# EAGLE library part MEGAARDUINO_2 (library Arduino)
The Arduino Mega is a microcontroller board based on the ATmega1280. - 54 digital input/output pins (of which 14 can be used as PWM outputs) - 16 analog inputs - 4 UARTs (hardware serial ports) - 16 MHz crystal oscillator - USB connection - power jack - ICSP header - reset button It contains everything needed to support the microcontroller; simply connect it to a computer with a USB cable or power it with a AC-to-DC adapter or battery to get started. The Mega is compatible with most shields designed for the Arduino Duemilanove or Diecimila. http://arduino.cc/en/Main/ArduinoBoardMega
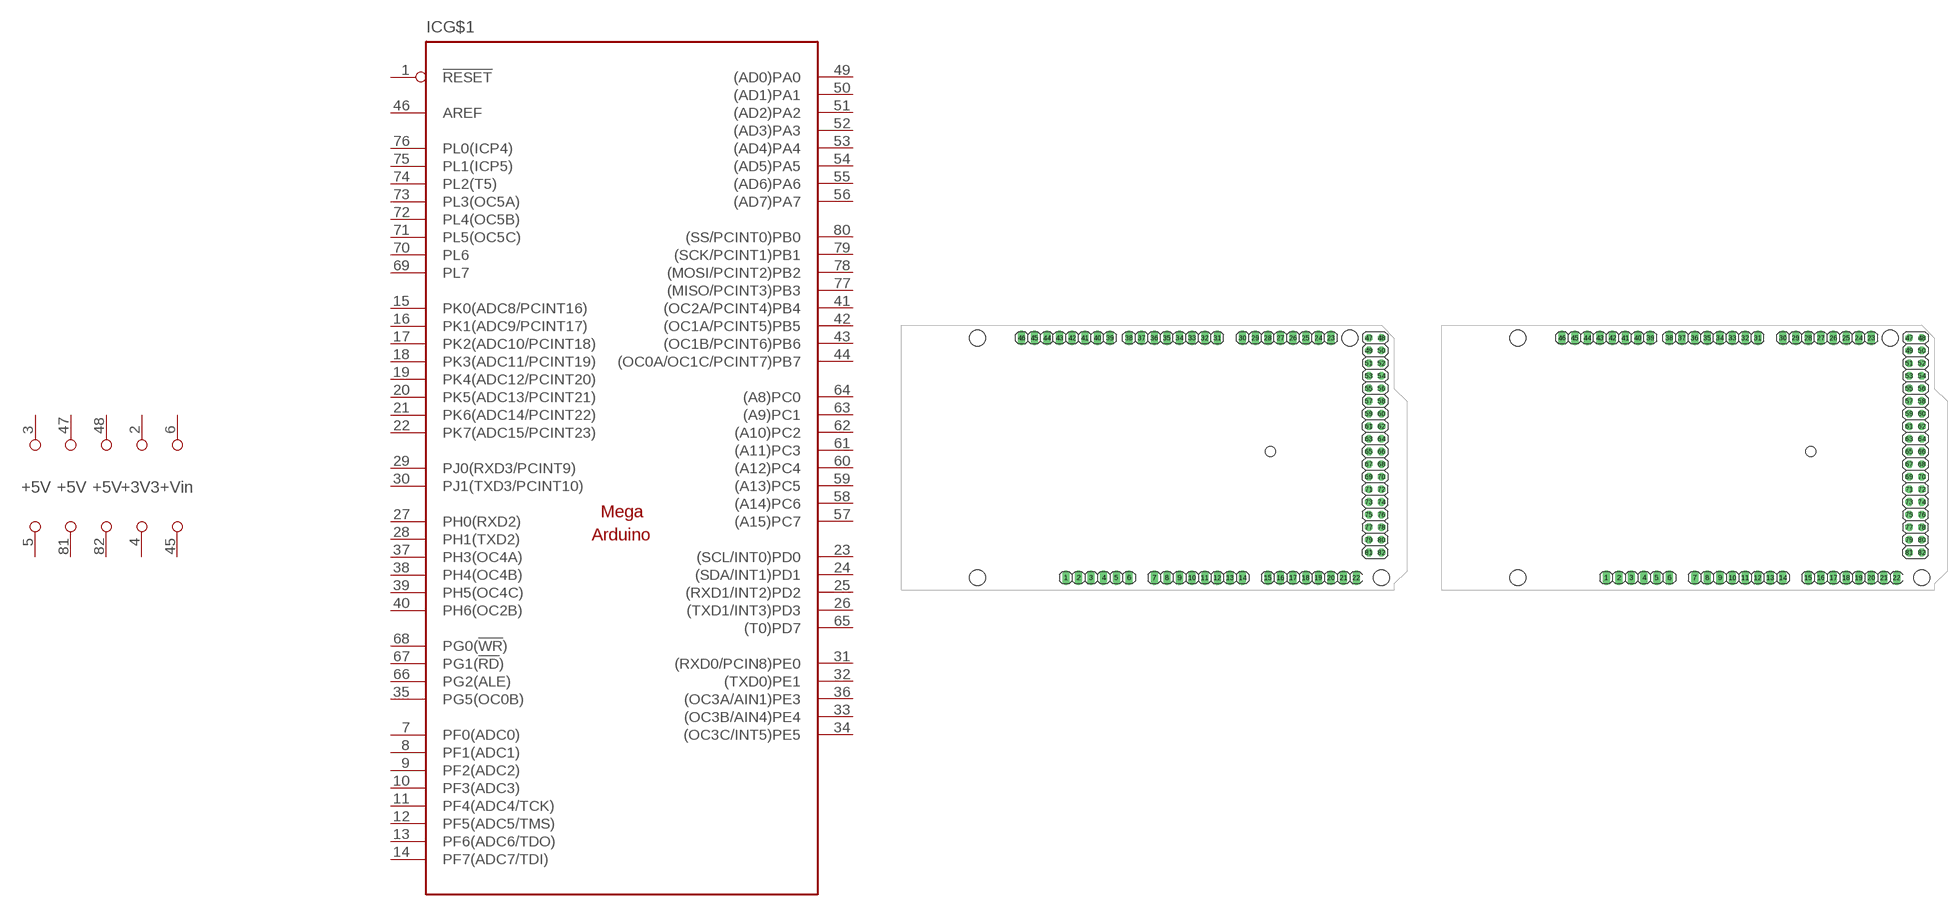
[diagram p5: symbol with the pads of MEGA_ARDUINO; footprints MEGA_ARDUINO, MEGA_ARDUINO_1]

Designator prefix IC; gates G$1=MEGAARDUINO_2 G$2=PWR5V G$3=PWR5V G$4=PWR5V G$5=PWR3V3 G$6=PWRVIN

## MEGAARDUINO_20  [MEGA_ARDUINO]
1  G$1:!RESET
2  G$5:+3V3  pwr
3  G$2:+5V  pwr
4  G$5:GND  pwr
5  G$2:GND  pwr
6  G$6:+VIN  pwr
7  G$1:PF0(ADC0)
8  G$1:PF1(ADC1)
9  G$1:PF2(ADC2)
10  G$1:PF3(ADC3)
11  G$1:PF4(ADC4/TCK)
12  G$1:PF5(ADC5/TMS)
13  G$1:PF6(ADC6/TDO)
14  G$1:PF7(ADC7/TDI)
15  G$1:PK0(ADC8/PCINT16)
16  G$1:PK1(ADC9/PCINT17)
17  G$1:PK2(ADC10/PCINT18)
18  G$1:PK3(ADC11/PCINT19)
19  G$1:PK4(ADC12/PCINT20)
20  G$1:PK5(ADC13/PCINT21)
21  G$1:PK6(ADC14/PCINT22)
22  G$1:PK7(ADC15/PCINT23)
23  G$1:(SCL/INT0)PD0
24  G$1:(SDA/INT1)PD1
25  G$1:(RXD1/INT2)PD2
26  G$1:(TXD1/INT3)PD3
27  G$1:PH0(RXD2)
28  G$1:PH1(TXD2)
29  G$1:PJ0(RXD3/PCINT9)
30  G$1:PJ1(TXD3/PCINT10)
31  G$1:(RXD0/PCIN8)PE0
32  G$1:(TXD0)PE1
33  G$1:(OC3B/AIN4)PE4
34  G$1:(OC3C/INT5)PE5
35  G$1:PG5(OC0B)
36  G$1:(OC3A/AIN1)PE3
37  G$1:PH3(OC4A)
38  G$1:PH4(OC4B)
39  G$1:PH5(OC4C)
40  G$1:PH6(OC2B)
41  G$1:(OC2A/PCINT4)PB4
42  G$1:(OC1A/PCINT5)PB5
43  G$1:(OC1B/PCINT6)PB6
44  G$1:(OC0A/OC1C/PCINT7)PB7
45  G$6:GND  pwr
46  G$1:AREF
47  G$3:+5V  pwr
48  G$4:+5V  pwr
49  G$1:(AD0)PA0
50  G$1:(AD1)PA1
51  G$1:(AD2)PA2
52  G$1:(AD3)PA3
53  G$1:(AD4)PA4
54  G$1:(AD5)PA5
55  G$1:(AD6)PA6
56  G$1:(AD7)PA7
57  G$1:(A15)PC7
58  G$1:(A14)PC6
59  G$1:(A13)PC5
60  G$1:(A12)PC4
61  G$1:(A11)PC3
62  G$1:(A10)PC2
63  G$1:(A9)PC1
64  G$1:(A8)PC0
65  G$1:(T0)PD7
66  G$1:PG2(ALE)
67  G$1:PG1(!RD!)
68  G$1:PG0(!WR!)
69  G$1:PL7
70  G$1:PL6
71  G$1:PL5(OC5C)
72  G$1:PL4(OC5B)
73  G$1:PL3(OC5A)
74  G$1:PL2(T5)
75  G$1:PL1(ICP5)
76  G$1:PL0(ICP4)
77  G$1:(MISO/PCINT3)PB3
78  G$1:(MOSI/PCINT2)PB2
79  G$1:(SCK/PCINT1)PB1
80  G$1:(SS/PCINT0)PB0
81  G$3:GND  pwr
82  G$4:GND  pwr

## MEGAARDUINO_21  [MEGA_ARDUINO_1]
Pads as for MEGA_ARDUINO

## MEGAARDUINO_22  [MEGA_ARDUINO_2]
Pads as for MEGA_ARDUINO

## Footprint MEGA_ARDUINO (pad centres in mm)
drill 1.016 long: 1 33.02,2.54; 2 35.56,2.54; 3 38.1,2.54; 4 40.64,2.54; 5 43.18,2.54; 6 45.72,2.54; 7 50.8,2.54; 8 53.34,2.54; 9 55.88,2.54; 10 58.42,2.54; 11 60.96,2.54; 12 63.5,2.54; 13 66.04,2.54; 14 68.58,2.54; 15 73.66,2.54; 16 76.2,2.54; 17 78.74,2.54; 18 81.28,2.54; 19 83.82,2.54; 20 86.36,2.54; 21 88.9,2.54; 22 91.44,2.54; 23 86.36,50.8; 24 83.82,50.8; 25 81.28,50.8; 26 78.74,50.8; 27 76.2,50.8; 28 73.66,50.8; 29 71.12,50.8; 30 68.58,50.8; 31 63.5,50.8; 32 60.96,50.8; 33 58.42,50.8; 34 55.88,50.8; 35 53.34,50.8; 36 50.8,50.8; 37 48.26,50.8; 38 45.72,50.8; 39 41.91,50.8; 40 39.37,50.8; 41 36.83,50.8; 42 34.29,50.8; 43 31.75,50.8; 44 29.21,50.8; 45 26.67,50.8; 46 24.13,50.8
drill 1.016 octagon: 47 93.98,50.8; 48 96.52,50.8; 49 93.98,48.26; 50 96.52,48.26; 51 93.98,45.72; 52 96.52,45.72; 53 93.98,43.18; 54 96.52,43.18; 55 93.98,40.64; 56 96.52,40.64; 57 93.98,38.1; 58 96.52,38.1; 59 93.98,35.56; 60 96.52,35.56; 61 93.98,33.02; 62 96.52,33.02; 63 93.98,30.48; 64 96.52,30.48; 65 93.98,27.94; 66 96.52,27.94; 67 93.98,25.4; 68 96.52,25.4; 69 93.98,22.86; 70 96.52,22.86; 71 93.98,20.32; 72 96.52,20.32; 73 93.98,17.78; 74 96.52,17.78; 75 93.98,15.24; 76 96.52,15.24; 77 93.98,12.7; 78 96.52,12.7; 79 93.98,10.16; 80 96.52,10.16; 81 93.98,7.62; 82 96.52,7.62
hole 3.2 at 15.24,50.8
hole 3.2 at 15.24,2.54
hole 3.2 at 90.17,50.8
hole 3.2 at 96.52,2.54
hole 2 at 74.168,27.94

## Footprint MEGA_ARDUINO_1 (pad centres in mm)
drill 1.016 long: 1 33.02,2.54; 2 35.56,2.54; 3 38.1,2.54; 4 40.64,2.54; 5 43.18,2.54; 6 45.72,2.54; 7 50.8,2.54; 8 53.34,2.54; 9 55.88,2.54; 10 58.42,2.54; 11 60.96,2.54; 12 63.5,2.54; 13 66.04,2.54; 14 68.58,2.54; 15 73.66,2.54; 16 76.2,2.54; 17 78.74,2.54; 18 81.28,2.54; 19 83.82,2.54; 20 86.36,2.54; 21 88.9,2.54; 22 91.44,2.54; 23 86.36,50.8; 24 83.82,50.8; 25 81.28,50.8; 26 78.74,50.8; 27 76.2,50.8; 28 73.66,50.8; 29 71.12,50.8; 30 68.58,50.8; 31 63.5,50.8; 32 60.96,50.8; 33 58.42,50.8; 34 55.88,50.8; 35 53.34,50.8; 36 50.8,50.8; 37 48.26,50.8; 38 45.72,50.8; 39 41.91,50.8; 40 39.37,50.8; 41 36.83,50.8; 42 34.29,50.8; 43 31.75,50.8; 44 29.21,50.8; 45 26.67,50.8; 46 24.13,50.8
drill 1.016 octagon: 47 93.98,50.8; 48 96.52,50.8; 49 93.98,48.26; 50 96.52,48.26; 51 93.98,45.72; 52 96.52,45.72; 53 93.98,43.18; 54 96.52,43.18; 55 93.98,40.64; 56 96.52,40.64; 57 93.98,38.1; 58 96.52,38.1; 59 93.98,35.56; 60 96.52,35.56; 61 93.98,33.02; 62 96.52,33.02; 63 93.98,30.48; 64 96.52,30.48; 65 93.98,27.94; 66 96.52,27.94; 67 93.98,25.4; 68 96.52,25.4; 69 93.98,22.86; 70 96.52,22.86; 71 93.98,20.32; 72 96.52,20.32; 73 93.98,17.78; 74 96.52,17.78; 75 93.98,15.24; 76 96.52,15.24; 77 93.98,12.7; 78 96.52,12.7; 79 93.98,10.16; 80 96.52,10.16; 81 93.98,7.62; 82 96.52,7.62
hole 3.2 at 15.24,50.8
hole 3.2 at 15.24,2.54
hole 3.2 at 90.17,50.8
hole 3.2 at 96.52,2.54
hole 2 at 74.168,27.94

## Footprint MEGA_ARDUINO_2 (pad centres in mm)
drill 1.016 long: 1 33.02,2.54; 2 35.56,2.54; 3 38.1,2.54; 4 40.64,2.54; 5 43.18,2.54; 6 45.72,2.54; 7 50.8,2.54; 8 53.34,2.54; 9 55.88,2.54; 10 58.42,2.54; 11 60.96,2.54; 12 63.5,2.54; 13 66.04,2.54; 14 68.58,2.54; 15 73.66,2.54; 16 76.2,2.54; 17 78.74,2.54; 18 81.28,2.54; 19 83.82,2.54; 20 86.36,2.54; 21 88.9,2.54; 22 91.44,2.54; 23 86.36,50.8; 24 83.82,50.8; 25 81.28,50.8; 26 78.74,50.8; 27 76.2,50.8; 28 73.66,50.8; 29 71.12,50.8; 30 68.58,50.8; 31 63.5,50.8; 32 60.96,50.8; 33 58.42,50.8; 34 55.88,50.8; 35 53.34,50.8; 36 50.8,50.8; 37 48.26,50.8; 38 45.72,50.8; 39 41.91,50.8; 40 39.37,50.8; 41 36.83,50.8; 42 34.29,50.8; 43 31.75,50.8; 44 29.21,50.8; 45 26.67,50.8; 46 24.13,50.8
drill 1.016 octagon: 47 93.98,50.8; 48 96.52,50.8; 49 93.98,48.26; 50 96.52,48.26; 51 93.98,45.72; 52 96.52,45.72; 53 93.98,43.18; 54 96.52,43.18; 55 93.98,40.64; 56 96.52,40.64; 57 93.98,38.1; 58 96.52,38.1; 59 93.98,35.56; 60 96.52,35.56; 61 93.98,33.02; 62 96.52,33.02; 63 93.98,30.48; 64 96.52,30.48; 65 93.98,27.94; 66 96.52,27.94; 67 93.98,25.4; 68 96.52,25.4; 69 93.98,22.86; 70 96.52,22.86; 71 93.98,20.32; 72 96.52,20.32; 73 93.98,17.78; 74 96.52,17.78; 75 93.98,15.24; 76 96.52,15.24; 77 93.98,12.7; 78 96.52,12.7; 79 93.98,10.16; 80 96.52,10.16; 81 93.98,7.62; 82 96.52,7.62
hole 3.2 at 15.24,50.8
hole 3.2 at 15.24,2.54
hole 3.2 at 90.17,50.8
hole 3.2 at 96.52,2.54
